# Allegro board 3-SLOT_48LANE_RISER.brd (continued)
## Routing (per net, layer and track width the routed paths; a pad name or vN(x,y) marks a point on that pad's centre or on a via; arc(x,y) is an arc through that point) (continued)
GND_L:
  vias: v2(-18.72,363.74) v2(-18.72,362.74) v2(-18.72,361.74) v2(-18.72,360.74) v2(-18.72,359.74) v2(-18.72,358.74) v2(-18.72,357.74) v2(-18.72,356.74) v2(-18.72,355.74) v2(-18.72,354.74) v2(-18.72,353.74) v2(-18.72,352.74) v2(-18.72,351.74) v2(-18.72,350.74) v2(-18.72,349.74) v2(-18.72,348.74) v2(-18.72,347.74) v2(-18.72,346.74) v2(-18.72,345.74) v2(-18.72,344.74) v2(-18.72,343.74) v2(-18.72,342.74) v2(-18.72,341.74) v2(-18.72,340.74) v2(-18.72,339.74) v2(-18.72,338.74) v2(-18.72,337.74) v2(-18.72,336.74) v2(-18.72,335.74) v2(-18.72,334.74) v2(-18.72,333.74) v2(-18.72,332.74) v2(-18.72,331.74) v2(-18.72,330.74) v2(-18.72,329.74) v2(-18.72,328.74) v2(-18.72,327.74) v2(-18.72,326.74) v2(-18.72,325.74) v2(-18.72,324.74) v2(-18.72,323.74) v2(-18.72,322.74) v2(-18.72,321.74) v2(-18.72,320.74) v2(-18.72,319.74) v2(-18.72,318.74) v2(-18.72,317.74) v2(-18.72,316.74) v2(-18.72,315.74) v2(-18.72,314.74) v2(-18.72,313.74) v2(-18.72,312.74) v2(-18.72,311.74) v2(-18.72,310.74) v2(-18.72,309.74) v2(-18.72,308.74) v2(-18.72,307.74) v2(-18.72,306.74) v2(-18.72,305.74) v2(-18.72,304.74) v2(-18.72,303.74) v2(-18.72,302.74) v2(-18.72,301.74) v2(-18.72,300.74) v2(-18.72,299.74) v2(-18.72,298.74) v2(-18.72,297.74) v2(-18.72,296.74) v2(-18.72,295.74) v2(-18.72,294.74) v2(-18.72,293.74) v2(-18.72,292.74) v2(-18.72,291.74) v2(-18.72,290.74) v2(-18.72,289.74) v2(-18.72,288.74) v2(-18.72,287.74) v2(-18.72,286.74) v2(-18.72,285.74) v2(-18.72,284.74) v2(-18.72,283.74) v2(-18.72,282.74) v2(-18.72,281.74) v2(-18.72,280.74) v2(-18.72,279.74) v2(-18.72,278.74) v2(-18.72,277.74) v2(-18.72,276.74) v2(-18.72,275.74) v2(-18.72,274.74) v2(-18.72,273.74) v2(-18.72,272.74) v2(-18.72,271.74) v2(-18.72,270.74) v2(-18.72,269.74) v2(-18.72,268.74) v2(-18.72,267.74) v2(-18.72,266.74) v2(-18.72,265.74) v2(-18.72,264.74) v2(-18.72,263.74) v2(-18.72,262.74) v2(-18.72,261.74) v2(-18.72,260.74) v2(-18.72,259.74) v2(-18.72,258.74) v2(-18.72,257.74) v2(-18.72,256.74) v2(-18.72,255.74) v2(-18.72,254.74) v2(-18.72,253.74) v2(-18.72,252.74) v2(-18.72,251.74) v2(-18.72,250.74) v2(-18.72,249.74) v2(-18.72,248.74) v2(-18.72,247.74) v2(-18.72,246.74) v2(-18.72,245.74) v2(-18.72,244.74) v2(-18.72,243.74) v2(-18.72,242.74) v2(-18.72,241.74) v2(-18.72,240.74) v2(-18.72,239.74) v2(-18.72,238.74) v2(-18.72,237.74) v2(-18.72,236.74) v2(-18.72,235.74) v2(-18.72,234.74) v2(-18.72,233.74) v2(-18.72,232.74) v2(-18.72,231.74) v2(-18.72,230.74) v2(-18.72,229.74) v2(-18.72,228.74) v2(-18.72,227.74) v2(-18.72,226.74) v2(-18.72,225.74) v2(-18.72,224.74) v2(-18.72,223.74) v2(-18.72,222.74) v2(-18.72,221.74) v2(-18.72,220.74) v2(-18.72,219.74) v2(-18.72,218.74) v2(-18.72,217.74) v2(-18.72,216.74) v2(-18.72,215.74) v2(-18.72,214.74) v2(-18.72,213.74) v2(-18.72,212.74) v2(-18.72,211.74) v2(-18.72,210.74) v2(-18.72,209.74) v2(-18.72,208.74) v2(-18.72,207.74) v2(-18.72,206.74) v2(-18.72,205.74) v2(-18.72,204.74) v2(-18.72,203.74) v2(-18.72,202.74) v2(-18.72,201.74) v2(-18.72,200.74) v2(-18.72,199.74) v2(-18.72,198.74) v2(-18.72,197.74) v2(-18.72,196.74) v2(-18.72,195.74) v2(-18.72,194.74) v2(-18.72,193.74) v2(-18.72,192.74) v2(-18.72,191.74) v2(-18.72,190.74) v2(-18.72,189.74) v2(-18.72,188.74) v2(-18.72,187.74) v2(-18.72,186.74) v2(-18.72,185.74) v2(-18.72,184.74) v2(-18.72,183.74) v2(-18.72,182.74) v2(-18.72,181.74) v2(-18.72,180.74) v2(-18.72,179.74) v2(-18.72,178.74) v2(-18.72,177.74) v2(-18.72,176.74) v2(-18.72,175.74) v2(-18.72,174.74) v2(-18.72,173.74) v2(-18.72,172.74) v2(-18.72,171.74) v2(-18.72,170.74) v2(-18.72,169.74) v2(-18.72,168.74) v2(-18.72,167.74) v2(-18.72,166.74) v2(-18.72,165.74) v2(-18.72,164.74) v2(-18.72,163.74) v2(-18.72,162.74) v2(-18.72,161.74) v2(-18.72,160.74) v2(-18.72,159.74) v2(-18.72,158.74) v2(-18.72,157.74) v2(-18.72,156.74) v2(-18.72,155.74) v2(-18.72,154.74) v2(-18.72,153.74) v2(-18.72,152.74) v2(-18.72,151.74) v2(-18.72,150.74) v2(-18.72,149.74) v2(-18.72,148.74) v2(-18.72,147.74) v2(-18.72,146.74) v2(-18.72,145.74) v2(-18.72,144.74) v2(-18.72,143.74) v2(-18.72,142.74) v2(-18.72,141.74) v2(-18.72,140.74) v2(-18.72,139.74) v2(-18.72,138.74) v2(-18.72,137.74) v2(-18.72,136.74) v2(-18.72,135.74) v2(-18.72,134.74) v2(-18.72,133.74) v2(-18.72,132.74) v2(-18.72,131.74) v2(-18.72,130.74) v2(-18.72,129.74) v2(-18.72,128.74) v2(-18.72,127.74) v2(-18.72,126.74) v2(-18.72,125.74) v2(-18.72,124.74) v2(-18.72,123.74) v2(-18.72,122.74) v2(-18.72,121.74) v2(-18.72,120.74) v2(-18.72,119.74) v2(-18.72,118.74) v2(-18.72,117.74) v2(-18.72,116.74) v2(-18.72,115.74) v2(-18.72,114.74) v2(-18.72,113.74) v2(-18.72,112.74) v2(-18.72,111.74) v2(-18.72,110.74) v2(-18.72,109.74) v2(-18.72,108.74) v2(-18.72,107.74) v2(-18.72,106.74) v2(-18.72,105.74) v2(-18.72,104.74) v2(-18.72,103.74) v2(-18.72,102.74) v2(-18.72,101.74) v2(-18.72,100.74) v2(-18.72,99.74) v2(-18.72,98.74) v2(-18.72,97.74) v2(-18.72,96.74) v2(-18.72,95.74) v2(-18.72,94.74) v2(-18.72,93.74) v2(-18.72,92.74) v2(-18.72,91.74) v2(-18.72,90.74) v2(-18.72,89.74) v2(-18.72,88.74) v2(-18.72,87.74) v2(-18.72,86.74) v2(-18.72,85.74) v2(-18.72,84.74) v2(-18.72,83.74) v2(-18.72,82.74) v2(-18.72,81.74) v2(-18.72,80.74) v2(-18.72,79.74) v2(-18.72,78.74) v2(-18.72,77.74) v2(-18.72,76.74) v2(-18.72,75.74) v2(-18.72,74.74) v2(-18.72,73.74) v2(-18.72,72.74) v2(-18.72,71.74) v2(-18.72,70.74) v2(-18.72,69.74) v2(-18.72,68.74) v2(-18.72,67.74) v2(-18.72,66.74) v2(-18.72,65.74) v2(-18.72,64.74) v2(-18.72,63.74) v2(-18.72,62.74) v2(-18.72,61.74) v2(-18.72,60.74) v2(-18.72,59.74) v2(-18.72,58.74) v2(-18.72,57.74) v2(-18.72,56.74) v2(-18.72,55.74) v2(-18.72,54.74) v2(-18.72,53.74) v2(-18.72,52.74) v2(-18.72,51.74) v2(-18.72,50.74) v2(-18.72,49.74) v2(-18.72,48.74) v2(-18.72,47.74) v2(-18.72,46.74) v2(-18.72,45.74) v2(-18.72,44.74) v2(-18.72,43.74) v2(-18.72,42.74) v2(-18.72,41.74) v2(-18.72,40.74) v2(-18.72,39.74) v2(-18.72,38.74) v2(-18.72,37.74) v2(-18.72,36.74) v2(-18.72,35.74) v2(-18.72,34.74) v2(-18.72,33.74) v2(-18.72,32.74) v2(-18.72,31.74) v2(-18.72,30.74) v2(-18.72,29.74) v2(-18.72,28.74) v2(-18.72,27.74) v2(-18.72,26.74) v2(-18.72,25.74) v2(-18.72,24.74) v2(-18.72,23.74) v2(-18.72,22.74) v2(-18.72,21.74) v2(-18.72,20.74) v2(-18.72,19.74) v2(-18.72,18.74) v2(-18.72,17.74) v2(-18.72,16.74) v2(-18.72,15.74) v2(-18.72,14.74) v2(-18.72,13.74) v2(-18.72,12.74) v2(-18.72,11.74) v2(-18.72,10.74) v2(-18.72,9.74) v2(-18.72,8.74) v2(-18.72,7.74) v2(-18.72,6.74) v2(-18.72,5.74) v2(-18.72,4.74) v2(-18.72,3.74) v2(-18.72,2.74) v2(-18.72,1.74) v2(-18.72,0.74) v2(-18.72,-0.26) v2(-18.72,-1.26) v2(-18.72,-2.26) v2(-18.72,-3.26) v2(-18.72,-4.26) v2(-18.72,-5.26) v2(-18.72,-6.26) v2(-18.72,-7.26) v2(-18.72,-8.26) v2(-17.1,65.8) v2(-17.1,64.8) v2(-17.1,63.8) v2(-17.1,62.8) v2(-17.1,61.8) v2(-17.1,60.8) v2(-17.1,59.8) v2(-17.1,58.8) v2(-17.1,57.8) v2(-17.1,56.8) v2(-17.1,55.8) v2(-17.1,54.8) v2(-17.1,53.8) v2(-17.1,52.8) v2(-17.1,51.8) v2(-17.1,50.8) v2(-16.97,299.48) v2(-16.97,298.48) v2(-16.97,297.48) v2(-16.97,296.48) v2(-16.97,295.48) v2(-16.97,294.48) v2(-16.97,293.48) v2(-16.97,292.48) v2(-16.97,291.48) v2(-16.97,290.48) v2(-16.97,289.48) v2(-16.97,288.48) v2(-16.97,287.48) v2(-16.97,286.48) v2(-16.97,285.48) v2(-16.97,284.48) v2(-16.97,237.38) v2(-16.97,236.38) v2(-16.97,235.38) v2(-16.97,234.38) v2(-16.97,233.38) v2(-16.97,232.38) v2(-16.97,231.38) v2(-16.97,230.38) v2(-16.97,229.38) v2(-16.97,228.38) v2(-16.97,227.38) v2(-16.97,4.21) v2(-16.97,3.21) v2(-16.97,2.21) v2(-16.97,1.21) v2(-16.97,0.21) v2(-16.97,-0.79) v2(-16.97,-1.79) v2(-16.97,-2.79) v2(-16.97,-3.79) v2(-16.97,-4.79) v2(-16.97,-5.79) v2(-16.97,-6.79) v2(-16.97,-7.79) v2(-16.85,180.36) v2(-16.85,179.36) v2(-16.85,178.36) v2(-16.85,177.36) v2(-16.85,176.36) v2(-16.85,175.36) v2(-16.85,174.36) v2(-16.85,173.36) v2(-16.85,172.36) v2(-16.85,171.36) v2(-16.85,170.36) v2(-16.85,122.95) v2(-16.85,121.95) v2(-16.85,120.95) v2(-16.85,119.95) v2(-16.85,118.95) v2(-16.85,117.95) v2(-16.85,116.95) v2(-16.85,115.95) v2(-16.85,114.95) v2(-16.85,113.95) v2(-16.85,112.95) v2(-16.72,363.74) v2(-16.72,362.74) v2(-16.72,361.74) v2(-16.72,360.74) v2(-16.72,359.74) v2(-16.72,358.74) v2(-16.72,357.74) v2(-16.72,356.74) v2(-16.72,355.74) v2(-16.72,354.74) v2(-16.72,353.74) v2(-16.72,352.74) v2(-16.72,351.74) v2(-16.72,350.74) v2(-16.72,349.74) v2(-16.72,348.74) v2(-16.72,347.74) v2(-16.72,346.74) v2(-15.1,65.8) v2(-15.1,64.8) v2(-15.1,63.8) v2(-15.1,62.8) v2(-15.1,61.8) v2(-15.1,60.8) v2(-15.1,59.8) v2(-15.1,58.8) v2(-15.1,57.8) v2(-15.1,56.8) v2(-15.1,55.8) v2(-15.1,54.8) v2(-15.1,53.8) v2(-15.1,52.8) v2(-15.1,51.8) v2(-15.1,50.8) v2(-14.97,299.48) v2(-14.97,298.48) v2(-14.97,297.48) v2(-14.97,296.48) v2(-14.97,295.48) v2(-14.97,294.48) v2(-14.97,293.48) v2(-14.97,292.48) v2(-14.97,291.48) v2(-14.97,290.48) v2(-14.97,289.48) v2(-14.97,288.48) v2(-14.97,287.48) v2(-14.97,286.48) v2(-14.97,285.48) v2(-14.97,284.48) v2(-14.97,237.38) v2(-14.97,236.38) v2(-14.97,235.38) v2(-14.97,234.38) v2(-14.97,233.38) v2(-14.97,232.38) v2(-14.97,231.38) v2(-14.97,230.38) v2(-14.97,229.38) v2(-14.97,228.38) v2(-14.97,227.38) v2(-14.97,4.21) v2(-14.97,3.21) v2(-14.97,2.21) v2(-14.97,1.21) v2(-14.97,0.21) v2(-14.97,-0.79) v2(-14.97,-1.79) v2(-14.97,-2.79) v2(-14.97,-3.79) v2(-14.97,-4.79) v2(-14.97,-5.79) v2(-14.97,-6.79) v2(-14.97,-7.79) v2(-14.85,180.36) v2(-14.85,179.36) v2(-14.85,178.36) v2(-14.85,177.36) v2(-14.85,176.36) v2(-14.85,175.36) v2(-14.85,174.36) v2(-14.85,173.36) v2(-14.85,172.36) v2(-14.85,171.36) v2(-14.85,170.36) v2(-14.85,122.95) v2(-14.85,121.95) v2(-14.85,120.95) v2(-14.85,119.95) v2(-14.85,118.95) v2(-14.85,117.95) v2(-14.85,116.95) v2(-14.85,115.95) v2(-14.85,114.95) v2(-14.85,113.95) v2(-14.85,112.95) v2(-14.72,363.74) v2(-14.72,362.74) v2(-14.72,361.74) v2(-14.72,360.74) v2(-14.72,359.74) v2(-14.72,358.74) v2(-14.72,357.74) v2(-14.72,356.74) v2(-14.72,355.74) v2(-14.72,354.74) v2(-14.72,353.74) v2(-14.72,352.74) v2(-14.72,351.74) v2(-14.72,350.74) v2(-14.72,349.74) v2(-14.72,348.74) v2(-14.72,347.74) v2(-14.72,346.74) v2(-13.1,65.8) v2(-13.1,64.8) v2(-13.1,63.8) v2(-13.1,62.8) v2(-13.1,61.8) v2(-13.1,60.8) v2(-13.1,59.8) v2(-13.1,58.8) v2(-13.1,57.8) v2(-13.1,56.8) v2(-13.1,55.8) v2(-13.1,54.8) v2(-13.1,53.8) v2(-13.1,52.8) v2(-13.1,51.8) v2(-13.1,50.8) v2(-12.97,299.48) v2(-12.97,298.48) v2(-12.97,297.48) v2(-12.97,296.48) v2(-12.97,295.48) v2(-12.97,294.48) v2(-12.97,293.48) v2(-12.97,292.48) v2(-12.97,291.48) v2(-12.97,290.48) v2(-12.97,289.48) v2(-12.97,288.48) v2(-12.97,287.48) v2(-12.97,286.48) v2(-12.97,285.48) v2(-12.97,284.48) v2(-12.97,237.38) v2(-12.97,236.38) v2(-12.97,235.38) v2(-12.97,234.38) v2(-12.97,233.38) v2(-12.97,232.38) v2(-12.97,231.38) v2(-12.97,230.38) v2(-12.97,229.38) v2(-12.97,228.38) v2(-12.97,227.38) v2(-12.97,4.21) v2(-12.97,3.21) v2(-12.97,2.21) v2(-12.97,1.21) v2(-12.97,0.21) v2(-12.97,-0.79) v2(-12.97,-1.79) v2(-12.97,-2.79) v2(-12.97,-3.79) v2(-12.97,-4.79) v2(-12.97,-5.79) v2(-12.97,-6.79) v2(-12.97,-7.79) v2(-12.85,180.36) v2(-12.85,179.36) v2(-12.85,178.36) v2(-12.85,177.36) v2(-12.85,176.36) v2(-12.85,175.36) v2(-12.85,174.36) v2(-12.85,173.36) v2(-12.85,172.36) v2(-12.85,171.36) v2(-12.85,170.36) v2(-12.85,122.95) v2(-12.85,121.95) v2(-12.85,120.95) v2(-12.85,119.95) v2(-12.85,118.95) v2(-12.85,117.95) v2(-12.85,116.95) v2(-12.85,115.95) v2(-12.85,114.95) v2(-12.85,113.95) v2(-12.85,112.95) v2(-12.72,363.74) v2(-12.72,362.74) v2(-12.72,361.74) v2(-12.72,360.74) v2(-12.72,359.74) v2(-12.72,358.74) v2(-12.72,357.74) v2(-12.72,356.74) v2(-12.72,355.74) v2(-12.72,354.74) v2(-12.72,353.74) v2(-12.72,352.74) v2(-12.72,351.74) v2(-12.72,350.74) v2(-12.72,349.74) v2(-12.72,348.74) v2(-12.72,347.74) v2(-12.72,346.74) v2(-11.1,65.8) v2(-11.1,64.8) v2(-11.1,63.8) v2(-11.1,62.8) v2(-11.1,61.8) v2(-11.1,60.8) v2(-11.1,59.8) v2(-11.1,58.8) v2(-11.1,57.8) v2(-11.1,56.8) v2(-11.1,55.8) v2(-11.1,54.8) v2(-11.1,53.8) v2(-11.1,52.8) v2(-11.1,51.8) v2(-11.1,50.8) v2(-10.97,299.48) v2(-10.97,298.48) v2(-10.97,297.48) v2(-10.97,296.48) v2(-10.97,295.48) v2(-10.97,294.48) v2(-10.97,293.48) v2(-10.97,292.48) v2(-10.97,291.48) v2(-10.97,290.48) v2(-10.97,289.48) v2(-10.97,288.48) v2(-10.97,287.48) v2(-10.97,286.48) v2(-10.97,285.48) v2(-10.97,284.48) v2(-10.97,237.38) v2(-10.97,236.38) v2(-10.97,235.38) v2(-10.97,234.38) v2(-10.97,233.38) v2(-10.97,232.38) v2(-10.97,231.38) v2(-10.97,230.38) v2(-10.97,229.38) v2(-10.97,228.38) v2(-10.97,227.38) v2(-10.97,4.21) v2(-10.97,3.21) v2(-10.97,2.21) v2(-10.97,1.21) v2(-10.97,0.21) v2(-10.97,-0.79) v2(-10.97,-1.79) v2(-10.97,-2.79) v2(-10.97,-3.79) v2(-10.97,-4.79) v2(-10.97,-5.79) v2(-10.97,-6.79) v2(-10.97,-7.79) v2(-10.85,180.36) v2(-10.85,179.36) v2(-10.85,178.36) v2(-10.85,177.36) v2(-10.85,176.36) v2(-10.85,175.36) v2(-10.85,174.36) v2(-10.85,173.36) v2(-10.85,172.36) v2(-10.85,171.36) v2(-10.85,170.36) v2(-10.85,122.95) v2(-10.85,121.95) v2(-10.85,120.95) v2(-10.85,119.95) v2(-10.85,118.95) v2(-10.85,117.95) v2(-10.85,116.95) v2(-10.85,115.95) v2(-10.85,114.95) v2(-10.85,113.95) v2(-10.85,112.95) v2(-10.72,363.74) v2(-10.72,362.74) v2(-10.72,361.74) v2(-10.72,360.74) v2(-10.72,359.74) v2(-10.72,358.74) v2(-10.72,357.74) v2(-10.72,356.74) v2(-10.72,355.74) v2(-10.72,354.74) v2(-10.72,353.74) v2(-10.72,352.74) v2(-10.72,351.74) v2(-10.72,350.74) v2(-10.72,349.74) v2(-10.72,348.74) v2(-10.72,347.74) v2(-10.72,346.74) v2(-9.1,65.8) v2(-9.1,64.8) v2(-9.1,63.8) v2(-9.1,62.8) v2(-9.1,61.8) v2(-9.1,60.8) v2(-9.1,59.8) v2(-9.1,58.8) v2(-9.1,57.8) v2(-9.1,56.8) v2(-9.1,55.8) v2(-9.1,54.8) v2(-9.1,53.8) v2(-9.1,52.8) v2(-9.1,51.8) v2(-9.1,50.8) v2(-8.97,299.48) v2(-8.97,298.48) v2(-8.97,297.48) v2(-8.97,296.48) v2(-8.97,295.48) v2(-8.97,294.48) v2(-8.97,293.48) v2(-8.97,292.48) v2(-8.97,291.48) v2(-8.97,290.48) v2(-8.97,289.48) v2(-8.97,288.48) v2(-8.97,287.48) v2(-8.97,286.48) v2(-8.97,285.48) v2(-8.97,284.48) v2(-8.97,237.38) v2(-8.97,236.38) v2(-8.97,235.38) v2(-8.97,234.38) v2(-8.97,233.38) v2(-8.97,232.38) v2(-8.97,231.38) v2(-8.97,230.38) v2(-8.97,229.38) v2(-8.97,228.38) v2(-8.97,227.38) v2(-8.97,4.21) v2(-8.97,3.21) v2(-8.97,2.21) v2(-8.97,1.21) v2(-8.97,0.21) v2(-8.97,-0.79) v2(-8.97,-1.79) v2(-8.97,-2.79) v2(-8.97,-3.79) v2(-8.97,-4.79) v2(-8.97,-5.79) v2(-8.97,-6.79) v2(-8.97,-7.79) v2(-8.85,180.36) v2(-8.85,179.36) v2(-8.85,178.36) v2(-8.85,177.36) v2(-8.85,176.36) v2(-8.85,175.36) v2(-8.85,174.36) v2(-8.85,173.36) v2(-8.85,172.36) v2(-8.85,171.36) v2(-8.85,170.36) v2(-8.85,122.95) v2(-8.85,121.95) v2(-8.85,120.95) v2(-8.85,119.95) v2(-8.85,118.95) v2(-8.85,117.95) v2(-8.85,116.95) v2(-8.85,115.95) v2(-8.85,114.95) v2(-8.85,113.95) v2(-8.85,112.95) v2(-8.72,363.74) v2(-8.72,362.74) v2(-8.72,361.74) v2(-8.72,360.74) v2(-8.72,359.74) v2(-8.72,358.74) v2(-8.72,357.74) v2(-8.72,356.74) v2(-8.72,355.74) v2(-8.72,354.74) v2(-8.72,353.74) v2(-8.72,352.74) v2(-8.72,351.74) v2(-8.72,350.74) v2(-8.72,349.74) v2(-8.72,348.74) v2(-8.72,347.74) v2(-8.72,346.74) v2(-8.18,164.21) v2(-7.42,164.21) v2(-7.1,65.8) v2(-7.1,64.8) v2(-7.1,63.8) v2(-7.1,62.8) v2(-7.1,61.8) v2(-7.1,60.8) v2(-7.1,59.8) v2(-7.1,58.8) v2(-7.1,57.8) v2(-7.1,56.8) v2(-7.1,55.8) v2(-7.1,54.8) v2(-7.1,53.8) v2(-7.1,52.8) v2(-7.1,51.8) v2(-7.1,50.8) v2(-6.97,299.48) v2(-6.97,298.48) v2(-6.97,297.48) v2(-6.97,296.48) v2(-6.97,295.48) v2(-6.97,294.48) v2(-6.97,293.48) v2(-6.97,292.48) v2(-6.97,291.48) v2(-6.97,290.48) v2(-6.97,289.48) v2(-6.97,288.48) v2(-6.97,287.48) v2(-6.97,286.48) v2(-6.97,285.48) v2(-6.97,284.48) v2(-6.97,237.38) v2(-6.97,236.38) v2(-6.97,235.38) v2(-6.97,234.38) v2(-6.97,233.38) v2(-6.97,232.38) v2(-6.97,231.38) v2(-6.97,230.38) v2(-6.97,229.38) v2(-6.97,228.38) v2(-6.97,227.38) v2(-6.97,4.21) v2(-6.97,3.21) v2(-6.97,2.21) v2(-6.97,1.21) v2(-6.97,0.21) v2(-6.97,-0.79) v2(-6.97,-1.79) v2(-6.97,-2.79) v2(-6.97,-3.79) v2(-6.97,-4.79) v2(-6.97,-5.79) v2(-6.97,-6.79) v2(-6.97,-7.79) v2(-6.85,180.36) v2(-6.85,179.36) v2(-6.85,178.36) v2(-6.85,177.36) v2(-6.85,176.36) v2(-6.85,175.36) v2(-6.85,174.36) v2(-6.85,173.36) v2(-6.85,172.36) v2(-6.85,171.36) v2(-6.85,170.36) v2(-6.85,122.95) v2(-6.85,121.95) v2(-6.85,120.95) v2(-6.85,119.95) v2(-6.85,118.95) v2(-6.85,117.95) v2(-6.85,116.95) v2(-6.85,115.95) v2(-6.85,114.95) v2(-6.85,113.95) v2(-6.85,112.95) v2(-6.72,363.74) v2(-6.72,362.74) v2(-6.72,361.74) v2(-6.72,358.74) v2(-6.72,357.74) v2(-6.72,356.74) v2(-6.72,355.74) v2(-6.72,354.74) v2(-6.72,353.74) v2(-6.72,352.74) v2(-6.72,351.74) v2(-6.72,348.74) v2(-6.72,347.74) v2(-6.72,346.74) v2(-4.96,65.8) v2(-4.96,64.8) v2(-4.96,63.8) v2(-4.96,62.8) v2(-4.96,61.8) v2(-4.96,60.8) v2(-4.96,59.8) v2(-4.96,58.8) v2(-4.96,57.8) v2(-4.96,56.8) v2(-4.96,55.8) v2(-4.96,54.8) v2(-4.96,53.8) v2(-4.96,52.8) v2(-4.96,51.8) v2(-4.96,50.8) v2(-4.83,299.48) v2(-4.83,298.48) v2(-4.83,297.48) v2(-4.83,296.48) v2(-4.83,295.48) v2(-4.83,294.48) v2(-4.83,293.48) v2(-4.83,292.48) v2(-4.83,291.48) v2(-4.83,290.48) v2(-4.83,289.48) v2(-4.83,288.48) v2(-4.83,287.48) v2(-4.83,286.48) v2(-4.83,285.48) v2(-4.83,284.48) v2(-4.83,237.38) v2(-4.83,236.38) v2(-4.83,235.38) v2(-4.83,234.38) v2(-4.83,233.38) v2(-4.83,232.38) v2(-4.83,231.38) v2(-4.83,230.38) v2(-4.83,229.38) v2(-4.83,228.38) v2(-4.83,227.38) v2(-4.83,4.21) v2(-4.83,3.21) v2(-4.83,-1.79) v2(-4.83,-6.79) v2(-4.83,-7.79) v2(-4.7,180.36) v2(-4.7,179.36) v2(-4.7,178.36) v2(-4.7,177.36) v2(-4.7,176.36) v2(-4.7,175.36) v2(-4.7,174.36) v2(-4.7,173.36) v2(-4.7,172.36) v2(-4.7,171.36) v2(-4.7,170.36) v2(-4.7,122.95) v2(-4.7,121.95) v2(-4.7,120.95) v2(-4.7,119.95) v2(-4.7,118.95) v2(-4.7,117.95) v2(-4.7,116.95) v2(-4.7,115.95) v2(-4.7,114.95) v2(-4.7,113.95) v2(-4.7,112.95) v2(-4.58,363.74) v2(-4.58,362.74) v2(-4.58,357.74) v2(-4.58,356.74) v2(-4.58,355.74) v2(-4.58,354.74) v2(-4.58,353.74) v2(-4.58,352.74) v2(-4.58,347.74) v2(-4.58,346.74) v2(-2.97,363.74) v2(-2.97,362.74) v2(-2.97,361.74) v2(-2.97,360.74) v2(-2.97,359.74) v2(-2.97,358.74) v2(-2.97,357.74) v2(-2.97,356.74) v2(-2.97,355.74) v2(-2.97,354.74) v2(-2.97,353.74) v2(-2.97,352.74) v2(-2.97,351.74) v2(-2.97,350.74) v2(-2.97,349.74) v2(-2.97,348.74) v2(-2.97,347.74) v2(-2.97,346.74) v2(-2.97,345.74) v2(-2.97,344.74) v2(-2.97,343.74) v2(-2.97,342.74) v2(-2.97,341.74) v2(-2.97,340.74) v2(-2.97,339.74) v2(-2.97,338.74) v2(-2.97,337.74) v2(-2.97,336.74) v2(-2.97,335.74) v2(-2.97,334.74) v2(-2.97,333.74) v2(-2.97,332.74) v2(-2.97,331.74) v2(-2.97,330.74) v2(-2.97,329.74) v2(-2.97,328.74) v2(-2.97,327.74) v2(-2.97,326.74) v2(-2.97,325.74) v2(-2.97,324.74) v2(-2.97,323.74) v2(-2.97,322.74) v2(-2.97,321.74) v2(-2.97,320.74) v2(-2.97,319.74) v2(-2.97,318.74) v2(-2.97,317.74) v2(-2.97,316.74) v2(-2.97,315.74) v2(-2.97,314.74) v2(-2.97,313.74) v2(-2.97,312.74) v2(-2.97,311.74) v2(-2.97,310.74) v2(-2.97,309.74) v2(-2.97,308.74) v2(-2.97,307.74) v2(-2.97,306.74) v2(-2.97,305.74) v2(-2.97,304.74) v2(-2.97,303.74) v2(-2.97,302.74) v2(-2.97,301.74) v2(-2.97,300.74) v2(-2.97,299.74) v2(-2.97,298.74) v2(-2.97,297.74) v2(-2.97,296.74) v2(-2.97,295.74) v2(-2.97,294.74) v2(-2.97,293.74) v2(-2.97,292.74) v2(-2.97,291.74) v2(-2.97,290.74) v2(-2.97,289.74) v2(-2.97,288.74) v2(-2.97,287.74) v2(-2.97,286.74) v2(-2.97,285.74) v2(-2.97,284.74) v2(-2.97,283.74) v2(-2.97,282.74) v2(-2.97,281.74) v2(-2.97,280.74) v2(-2.97,279.74) v2(-2.97,278.74) v2(-2.97,277.74) v2(-2.97,276.74) v2(-2.97,275.74) v2(-2.97,274.74) v2(-2.97,273.74) v2(-2.97,272.74) v2(-2.97,271.74) v2(-2.97,270.74) v2(-2.97,269.74) v2(-2.97,268.74) v2(-2.97,267.74) v2(-2.97,266.74) v2(-2.97,265.74) v2(-2.97,264.74) v2(-2.97,263.74) v2(-2.97,262.74) v2(-2.97,261.74) v2(-2.97,260.74) v2(-2.97,259.74) v2(-2.97,258.74) v2(-2.97,257.74) v2(-2.97,256.74) v2(-2.97,255.74) v2(-2.97,254.74) v2(-2.97,253.74) v2(-2.97,252.74) v2(-2.97,251.74) v2(-2.97,250.74) v2(-2.97,249.74) v2(-2.97,248.74) v2(-2.97,247.74) v2(-2.97,246.74) v2(-2.97,245.74) v2(-2.97,244.74) v2(-2.97,243.74) v2(-2.97,242.74) v2(-2.97,241.74) v2(-2.97,240.74) v2(-2.97,239.74) v2(-2.97,238.74) v2(-2.97,237.74) v2(-2.97,236.74) v2(-2.97,235.74) v2(-2.97,234.74) v2(-2.97,233.74) v2(-2.97,232.74) v2(-2.97,231.74) v2(-2.97,230.74) v2(-2.97,229.74) v2(-2.97,228.74) v2(-2.97,227.74) v2(-2.97,226.74) v2(-2.97,225.74) v2(-2.97,224.74) v2(-2.97,223.74) v2(-2.97,222.74) v2(-2.97,221.74) v2(-2.97,220.74) v2(-2.97,219.74) v2(-2.97,218.74) v2(-2.97,217.74) v2(-2.97,216.74) v2(-2.97,215.74) v2(-2.97,214.74) v2(-2.97,213.74) v2(-2.97,212.74) v2(-2.97,211.74) v2(-2.97,210.74) v2(-2.97,209.74) v2(-2.97,208.74) v2(-2.97,207.74) v2(-2.97,206.74) v2(-2.97,205.74) v2(-2.97,204.74) v2(-2.97,203.74) v2(-2.97,202.74) v2(-2.97,201.74) v2(-2.97,200.74) v2(-2.97,199.74) v2(-2.97,198.74) v2(-2.97,197.74) v2(-2.97,196.74) v2(-2.97,195.74) v2(-2.97,194.74) v2(-2.97,193.74) v2(-2.97,192.74) v2(-2.97,191.74) v2(-2.97,190.74) v2(-2.97,189.74) v2(-2.97,188.74) v2(-2.97,187.74) v2(-2.97,186.74) v2(-2.97,185.74) v2(-2.97,184.74) v2(-2.97,183.74) v2(-2.97,182.74) v2(-2.97,181.74) v2(-2.97,180.74) v2(-2.97,179.74) v2(-2.97,178.74) v2(-2.97,177.74) v2(-2.97,176.74) v2(-2.97,175.74) v2(-2.97,174.74) v2(-2.97,173.74) v2(-2.97,172.74) v2(-2.97,171.74) v2(-2.97,170.74) v2(-2.97,169.74) v2(-2.97,168.74) v2(-2.97,167.74) v2(-2.97,166.74) v2(-2.97,165.74) v2(-2.97,164.74) v2(-2.97,163.74) v2(-2.97,162.74) v2(-2.97,161.74) v2(-2.97,160.74) v2(-2.97,159.74) v2(-2.97,158.74) v2(-2.97,157.74) v2(-2.97,156.74) v2(-2.97,155.74) v2(-2.97,154.74) v2(-2.97,153.74) v2(-2.97,152.74) v2(-2.97,151.74) v2(-2.97,150.74) v2(-2.97,149.74) v2(-2.97,148.74) v2(-2.97,147.74) v2(-2.97,146.74) v2(-2.97,145.74) v2(-2.97,144.74) v2(-2.97,143.74) v2(-2.97,142.74) v2(-2.97,141.74) v2(-2.97,140.74) v2(-2.97,139.74) v2(-2.97,138.74) v2(-2.97,137.74) v2(-2.97,136.74) v2(-2.97,135.74) v2(-2.97,134.74) v2(-2.97,133.74) v2(-2.97,132.74) v2(-2.97,131.74) v2(-2.97,130.74) v2(-2.97,129.74) v2(-2.97,128.74) v2(-2.97,127.74) v2(-2.97,126.74) v2(-2.97,125.74) v2(-2.97,124.74) v2(-2.97,123.74) v2(-2.97,122.74) v2(-2.97,121.74) v2(-2.97,120.74) v2(-2.97,119.74) v2(-2.97,118.74) v2(-2.97,117.74) v2(-2.97,116.74) v2(-2.97,115.74) v2(-2.97,114.74) v2(-2.97,113.74) v2(-2.97,112.74) v2(-2.97,111.74) v2(-2.97,110.74) v2(-2.97,109.74) v2(-2.97,108.74) v2(-2.97,107.74) v2(-2.97,106.74) v2(-2.97,105.74) v2(-2.97,104.74) v2(-2.97,103.74) v2(-2.97,102.74) v2(-2.97,101.74) v2(-2.97,100.74) v2(-2.97,99.74) v2(-2.97,98.74) v2(-2.97,97.74) v2(-2.97,96.74) v2(-2.97,95.74) v2(-2.97,94.74) v2(-2.97,93.74) v2(-2.97,92.74) v2(-2.97,91.74) v2(-2.97,90.74) v2(-2.97,89.74) v2(-2.97,88.74) v2(-2.97,87.74) v2(-2.97,86.74) v2(-2.97,85.74) v2(-2.97,84.74) v2(-2.97,83.74) v2(-2.97,82.74) v2(-2.97,81.74) v2(-2.97,80.74) v2(-2.97,79.74) v2(-2.97,78.74) v2(-2.97,77.74) v2(-2.97,76.74) v2(-2.97,75.74) v2(-2.97,74.74) v2(-2.97,73.74) v2(-2.97,72.74) v2(-2.97,71.74) v2(-2.97,70.74) v2(-2.97,69.74) v2(-2.97,68.74) v2(-2.97,67.74) v2(-2.97,66.74) v2(-2.97,65.74) v2(-2.97,64.74) v2(-2.97,63.74) v2(-2.97,62.74) v2(-2.97,61.74) v2(-2.97,60.74) v2(-2.97,59.74) v2(-2.97,58.74) v2(-2.97,57.74) v2(-2.97,56.74) v2(-2.97,55.74) v2(-2.97,54.74) v2(-2.97,53.74) v2(-2.97,52.74) v2(-2.97,51.74) v2(-2.97,50.74) v2(-2.97,49.74) v2(-2.97,48.74) v2(-2.97,47.74) v2(-2.97,46.74) v2(-2.97,45.74) v2(-2.97,44.74) v2(-2.97,43.74) v2(-2.97,42.74) v2(-2.97,41.74) v2(-2.97,40.74) v2(-2.97,39.74) v2(-2.97,38.74) v2(-2.97,37.74) v2(-2.97,36.74) v2(-2.97,35.74) v2(-2.97,34.74) v2(-2.97,33.74) v2(-2.97,32.74) v2(-2.97,31.74) v2(-2.97,30.74) v2(-2.97,29.74) v2(-2.97,28.74) v2(-2.97,27.74) v2(-2.97,26.74) v2(-2.97,25.74) v2(-2.97,24.74) v2(-2.97,23.74) v2(-2.97,22.74) v2(-2.97,21.74) v2(-2.97,20.74) v2(-2.97,19.74) v2(-2.97,18.74) v2(-2.97,17.74) v2(-2.97,16.74) v2(-2.97,15.74) v2(-2.97,14.74) v2(-2.97,13.74) v2(-2.97,12.74) v2(-2.97,11.74) v2(-2.97,10.74) v2(-2.97,9.74) v2(-2.97,8.74) v2(-2.97,7.74) v2(-2.97,6.74) v2(-2.97,5.74) v2(-2.97,4.74) v2(-2.97,3.74) v2(-2.97,2.74) v2(-2.97,1.74) v2(-2.97,0.74) v2(-2.97,-0.26) v2(-2.97,-1.26) v2(-2.97,-2.26) v2(-2.97,-3.26) v2(-2.97,-4.26) v2(-2.97,-5.26) v2(-2.97,-6.26) v2(-2.97,-7.26) v2(-2.97,-8.26)
P0V9: length 287.7
  TOP w0.203: C18.1 v3(64.85,73.56) ; C271.1 v3(60.85,73.56) ; C402.1 v3(61.65,76.77) C430.1 ; C290.1 v3(61.65,72.76) ; C418.1 v3(64.05,74.36) ; C422.1 v3(60.05,76.77) ; C16.1 v3(63.25,79.17) C438.1 ; C22.1 v3(60.85,79.17) ; C20.1 v3(64.05,78.37) ; C279.1 v3(60.05,74.36) ; C273.1 v3(60.85,71.96) ; C9.1 v3(59.25,79.17) ; C269.1 v3(60.85,77.57) ; C287.1 v3(63.25,71.96) ; C275.1 v3(63.25,77.57) C283.1 ; C297.1 v3(63.25,73.56) ; C394.1 v3(63.25,75.16) ; C398.1 v3(60.05,78.37) ; C426.1 v3(60.85,75.16) ; C277.1 v3(64.05,72.76) ; C442.1 v3(59.25,73.56) ; C281.1 v3(60.05,72.76) ; C294.1 v3(61.65,74.36) ; C434.1 v3(64.05,76.77) ; C410.1 v3(61.65,78.37) ; C414.1 v3(64.85,75.16)
  TOP w0.254: v2(49.48,61.09) 49.45,61.09 48.56,60.2 47.32,60.2 PR433.2 ; 59.57,72.18 v3(59.25,71.96)
  TOP w0.381: R148.1 v2(258.19,29.92) ; C145.1 v5(71.45,65.02) ; C147.1 v5(73.23,64.41)
  TOP w0.762: v2(116.89,42.49) 80.9,42.49 73,50.39 61.95,50.39 61.16,51.18
  IN1 w0.254: v2(47.96,61.34) 48.21,61.59 48.21,63.66 49.58,65.02 53.42,65.02 53.43,65.01 53.84,65.01 54.21,64.64 59.05,64.64 62.26,67.85 62.26,72.16 v3(61.65,72.76)
  IN1 w0.762: v2(258.19,29.92) 257.68,29.41 187.68,29.41 171.6,45.49 119.89,45.49 v2(116.89,42.49)
  IN2 w0.254: v2(59.51,53.09) 62.18,53.09 66.35,48.92 69.7,48.92 69.95,48.67 v2(69.95,48.39)
  BOTTOM w0.254: v3(60.85,71.96) U1.P8 ; U1.L13 v3(64.05,76.77) U1.K14 ; v3(63.25,73.56) 62.85,73.96 U1.M10 ; U1.P14 61.25,77.17 v3(60.85,77.57) ; U1.K12 v3(64.85,75.16) ; U1.R9 v3(60.05,72.76) U1.T8 v3(59.25,71.96) ; PR430.2 69.95,47.63 v2(69.95,48.39) ; U1.M14 v3(63.25,77.57) 63.65,77.96 U1.L15 v3(64.05,78.37) U1.K16 ; U1.R11 v3(60.05,74.36) ; U1.P12 v3(60.85,75.16) ; U1.N11 v3(61.65,74.36) ; U1.N9 v3(61.65,72.76) ; PR433.2 47.57,59.94 47.96,59.94 48.21,60.2 48.21,61.09 v2(47.96,61.34) ; U1.L11 v3(64.05,74.36) ; U1.M12 v3(63.25,75.16) ; v3(60.85,79.17) 61.25,78.77 U1.P16 ; U1.T10 59.65,73.96 v3(59.25,73.56) ; U1.M16 v3(63.25,79.17) ; U1.R15 v3(60.05,78.37) ; U1.K10 v3(64.85,73.56) ; v3(60.85,73.56) 61.25,73.96 U1.P10 ; U1.T14 v3(60.05,76.77) U1.R13 U1.T12 ; U1.M8 62.85,72.36 v3(63.25,71.96) ; v3(59.25,79.17) 59.65,78.77 U1.T16 ; U1.L9 v3(64.05,72.76) U1.K8 ; U1.N13 v3(61.65,76.77) ; U1.N15 v3(61.65,78.37)
  vias: v2(23.19,89.66) v2(23.32,87.88) v2(23.32,86.36) v2(23.95,89.66) v2(24.08,87.88) v2(24.08,86.36) v2(24.72,89.66) v2(24.84,87.88) v2(24.84,86.36) v2(45.42,51.59) v2(45.92,52.07) v2(45.92,50.93) v2(46.18,52.96) v2(47.07,53.09) v2(48.46,53.09) v2(49.48,62.1) v2(49.61,53.09) v2(49.61,51.82) v2(49.61,50.67) v2(50.5,50.67) v2(50.62,53.09) v2(50.62,51.82) v2(50.75,63.12) v2(51.51,53.09) v2(51.69,62.03) v2(51.69,61.01) v2(52.66,53.09) v2(53.54,53.09) v2(53.85,61.93) v2(53.85,61.09) v2(54.43,53.09) v2(54.56,52.07) v2(54.56,50.67) v2(55.45,53.09) v2(55.45,52.07) v2(55.45,50.67) v2(56.72,53.09) v2(57.74,53.09) v2(59.79,51.97) v2(59.79,50.57) v4(48.08,51.18) v4(55.81,63.37) v4(58.22,51.74)
P0V9_A: length 48.5
  TOP w0.203: C164.1 v3(60.85,71.16) ; C150.1 v3(58.45,71.96) ; C19.1 v3(66.45,71.96) ; C141.1 v3(66.45,75.16) ; C15.1 v3(58.45,72.76) ; C144.1 v3(64.85,79.17) ; C146.1 v3(65.65,78.37) ; v3(65.65,72.76) C10.1 ; C161.1 v3(66.45,79.17) ; C142.1 v3(64.85,70.36) ; C21.1 v3(66.45,72.76) ; C4.1 v3(57.65,75.97) ; v3(58.45,79.17) C17.1 ; C151.1 v3(66.45,79.97) ; v3(58.45,74.36) C6.1 ; C163.1 v3(63.25,71.16) ; C2.1 v3(57.65,78.37) ; C148.1 v3(66.45,70.36) ; C14.1 v3(65.65,74.36) ; C162.1 v3(58.45,80.77) ; C5.1 v3(59.25,80.77) ; C7.1 v3(58.45,78.37)
  TOP w0.254: v3(63.25,79.97) 63.21,80.01 C406.1 ; v3(58.45,77.57) 59.57,77.76 59.57,77.77 C390.1 ; C143.1 v3(65.65,76.77) ; C194.1 v3(60.05,71.16)
  TOP w0.381: C11.1 v2(43.13,89.92) ; C8.1 v2(72.59,88.14) ; C188.1 v2(43.13,92.02) ; C3.1 v2(66.37,88.14) ; C177.1 v2(43.13,86.87) ; C12.1 v2(75.01,88.14) ; C184.1 v2(43.13,87.88) ; C149.1 v2(43.13,91.01) ; C13.1 v2(43.13,88.9) ; C160.1 v2(71.2,88.14)
  BOTTOM w0.254: v3(65.65,78.37) U1.H16 v3(66.45,79.17) ; v3(65.65,78.37) U1.H15 ; v3(65.65,78.37) U1.J15 ; v3(65.65,72.76) U1.H9 v3(66.45,72.76) U1.H8 v3(66.45,71.96) 66.06,71.57 U1.H7 v3(66.45,71.16) 66.06,70.76 U1.H6 v3(66.45,70.36) ; v3(65.65,72.76) 65.26,72.37 U1.J8 65.25,72.36 v3(64.85,71.96) U1.J7 ; v3(65.65,72.76) U1.J9 ; U1.N7 U1.M7 ; v3(58.45,72.76) 58.85,72.37 U1.U8 v3(58.45,71.96) ; U1.K17 64.46,79.56 v3(64.85,79.17) 65.25,78.77 U1.J16 ; U1.K6 v3(64.85,70.36) ; v3(58.45,80.77) U1.U18 v3(59.25,80.77) U1.T18 ; U1.V12 58.05,75.57 v3(57.65,75.97) ; U1.H12 v3(66.45,75.16) ; U1.J11 v3(65.65,74.36) ; U1.R7 v3(60.85,71.16) ; U1.J18 v3(64.85,80.77) U1.K18 64.05,80.76 v3(64.05,80.77) U1.L18 63.65,80.36 v3(63.25,79.97) U1.M17 U1.N17 ; U1.T6 v3(60.05,71.16) ; U1.R6 v3(60.05,70.36) ; U1.J13 v3(65.65,76.77) ; U1.H17 v3(66.45,79.97)
  BOTTOM w0.279: U1.M7 v3(63.25,71.16) ; U1.U11 v3(58.45,74.36) ; U1.U9 v3(58.45,72.76)
  BOTTOM w0.356: U1.U14 v3(58.45,77.57)
  BOTTOM w0.381: v3(58.45,78.37) U1.V15 v3(58.45,77.57) ; v3(58.45,78.37) U1.U15 ; v3(58.45,78.37) U1.U16 v3(58.45,79.17) ; U1.U17 v3(58.45,79.17) ; v3(58.45,79.17) 58.05,78.77 U1.V16 v3(57.65,78.37)
  vias: v2(29.54,89.03) v2(29.54,88.27) v2(29.54,87.38) v2(29.54,86.49) v2(30.56,89.03) v2(30.56,88.27) v2(30.56,87.38) v2(30.56,86.49) v2(42.04,91.08) v2(42.04,90.37) v2(41.99,89.56) v2(42.45,88.87) v2(42.42,88.11) v2(42.47,87.43) v4(33.02,92.46)
P0V9_AGND: length 4.1
  TOP w0.305: v2(67.94,43.01) PU23.4 69.45,43.03 70.16,43.03 v2(70.32,43.18) 71.96,43.18 PR423.2
P0V9_COMP: length 6.6
  TOP w0.254: PR427.1 73.44,43.71 v1(73.2,43.95) 72.78,43.53 72.78,42.54 72.53,42.28 PC589.1 70.71,42.6 70.05,42.6 69.82,42.36 PU23.3
P0V9_COMP_RC: length 2.6
  TOP w0.254: PR427.2 74.24,41.72 v1(74.01,41.49) 73.03,41.49 PC591.1
P0V9_EN: length 7.6
  TOP w0.203: v2(70.19,38.24) 70.11,38.32 70.11,38.85 69.25,39.72 68.28,39.72 67.95,40.05 PU23.15
  TOP w0.254: PC580.1 70.8,37.64 v2(70.19,38.24)
  BOTTOM w0.254: v2(70.19,38.24) 70.68,38.73 v4(71.32,38.73) 71.34,38.72 PR418.2
P0V9_FB: length 7.8
  TOP w0.254: PC589.2 71.25,41.72 PC591.2 ; PC589.2 PR431.1 72.24,40.53 v1(72.25,40.51) 72.47,40.3 PR432.1 ; PC589.2 70.84,41.48 70.57,41.22 70.46,41.22 v2(70.31,41.06) PU23.1
  BOTTOM w0.254: PR429.2 69.31,41.91 70.16,41.06 v2(70.31,41.06)
P0V9_FB_RC: length 2.8
  TOP w0.254: PR431.2 71.02,38.69 v1(71.17,38.54) 71.91,39.27 PC597.1
P0V9_PG: length 281.9
  TOP w0.114: PR420.2 v2(71.44,47.72) ; v2(300.79,24.1) 302.88,22.01 Q7.G ; v2(298.27,42.75) 298.12,42.75 294.7,46.17 R297.1
  TOP w0.254: PU23.7 69.63,44.96 69.75,45.09 69.75,45.82 70.98,47.05 PR420.2
  IN2 w0.147: v2(300.79,24.1) 300.79,28.24 298.27,30.76 v2(298.27,42.75)
  BOTTOM w0.114: v2(300.79,24.1) 297.77,24.1 296.39,22.73 291.62,22.73 291.14,22.25 282.53,22.25 281.69,23.09 274.63,23.09 272.95,24.77 268.23,24.77 266.7,26.29 189.13,26.29 168.78,46.63 118.42,46.63 115.29,43.51 74.73,43.51 71.44,46.8 v2(71.44,47.72)
P0V9_PG_LED_H: length 2.2
  TOP w0.114: R110.1 304.64,25.4 v2(305.26,25.4) 305.64,25.78 D1.A
P0V9_PG_LED_N: length 4.6
  TOP w0.114: Q7.D 305.6,23.62 v2(306.91,23.62) 307.27,23.98 R109.2 307.27,25.15 307.66,25.53 D1.C
P0V9_RT: length 2.8
  TOP w0.254: PU23.5 69.83,43.66 70.3,44.14 v1(70.76,44.14) 71.88,44.14 PR423.1
P0V9_SENSE_R_N: length 68.8
  TOP w0.254: PR505.1 46.03,59.66 45.52,59.66 v2(45.34,59.49)
  BOTTOM w0.254: PR428.1 68.34,43.74 PR504.2 68.53,43.54 68.53,42.06 PR429.1 68.43,41.87 68.43,41.71 68.9,41.24 69.28,41.24 70.05,40.46 71.5,40.46 v4(72.62,39.34) 72.62,38.38 73.74,37.26 73.74,36.68 71.6,34.54 47.25,34.54 45.14,36.66 45.14,45.31 44.27,46.18 44.27,59.26 44.71,59.69 45.14,59.69 v2(45.34,59.49) 45.52,59.66 46.03,59.66 PR505.1
P0V9_SENSE_R_P: length 63.3
  TOP w0.254: v2(45.37,60.25) 45.54,60.07 46.29,60.07 PR433.1 ; PC597.2 v2(73.59,38.47) 73.59,39.37 PR432.2
  BOTTOM w0.254: PR433.1 46.29,60.07 45.54,60.07 v2(45.37,60.25) 45.19,60.07 44.55,60.07 43.89,59.42 43.89,46.02 44.76,45.16 44.76,36.5 47.09,34.16 71.76,34.16 74.12,36.53 74.12,37.94 v2(73.59,38.47)
P0V9_VCC: length 9
  TOP w0.254: v2(67.41,46.58) 67.3,46.47 PU23.10 ; PU23.6 69.84,44.31 70.79,45.26 v7(70.79,45.68)
  TOP w0.381: v2(67.41,46.58) 67.41,47.27 PC581.2
  IN1 w0.254: v7(70.79,45.68) 70.31,45.2 68.06,45.2 67.6,45.66 67.6,46.39 v2(67.41,46.58)
P0V9_VIN: length 4.1
  TOP w0.254: PU23.9 67.95,46.38 v2(68.12,46.55)
  TOP w0.381: PC583.1 68.41,46.85 v2(68.12,46.55)
  BOTTOM w0.508: v2(68.12,46.55) 68.12,47.45 PR426.2
P0V9_VREF: length 2.2
  TOP w0.254: v2(70.31,41.88) 70.25,41.88 70.08,41.71 PU23.2
  BOTTOM w0.254: PC582.1 70.56,42.14 70.31,41.89 v2(70.31,41.88)
P0V9_VSNS: length 4.5
  TOP w0.254: v2(69.49,46.35) 69.03,46.35 68.6,45.92 PU23.8
  BOTTOM w0.254: PR428.2 68.34,45.63 69.04,46.34 69.48,46.34 v2(69.49,46.35) 69.49,46.82 69.2,47.11 PR430.1
P1V8: length 301.8
  TOP w0.203: 65.44,80.28 v3(65.65,79.97) ; v3(61.65,80.77) 61.42,81 C131.1 ; C135.1 v3(59.25,71.16) ; C53.1 v3(61.65,70.36) ; C133.1 v3(64.85,71.16) ; C139.1 v3(59.25,79.97)
  TOP w0.254: v3(61.65,80.77) 61.67,80.75 R57.1 ; C129.1 58.5,75.21 v3(58.45,75.16) ; C181.1 v3(65.65,75.16) ; U12.1 v2(121.07,39.22)
  TOP w0.356: U13.5 158.21,113.78 158.47,113.53 C191.1 ; R60.1 R62.1
  TOP w0.381: v2(65.74,62.87) 65.36,63.25 R94.1 ; v2(63.98,100.69) C1.1 64.85,100.33 64.34,99.82 U6.8 ; R47.1 61.04,63.12 v2(61.16,62.99) ; R113.1 v2(23.83,108.97) ; R51.1 v2(30.18,108.97) ; R117.1 v2(56.97,93.34) R70.1 ; R49.1 v2(33.22,106.93) R69.1 ; R54.1 R50.1 58.88,63.32 59.26,62.94 v2(59.64,62.94) ; R52.1 v2(25.86,106.81) ; C191.1 158.47,111.99 v2(158.57,111.89) ; v2(54.81,62.94) R74.1 R72.1 ; R64.1 v2(35,108.35) ; C127.1 v2(52.66,95.38) ; R55.1 v2(24.84,106.81) R56.1 ; v2(62.82,62.99) 63.07,63.25 R53.1 ; v2(258.24,27.15) 258.52,26.87 R146.1 ; v2(63.81,87.93) 64.21,88.34 R128.1 R121.1 ; v2(77.93,74.17) 77.67,74.42 R60.1 ; R129.1 v2(66.73,101.49) ; R48.1 v2(57.99,95.38) ; R111.1 v2(68.4,62.89) ; R351.1 v2(165.3,114.7) ; R46.1 v2(70.44,62.89) ; R115.1 v2(53.67,95.38) ; R93.1 v2(69.42,62.89)
  TOP w0.457: v2(70.46,91.69) 70.46,92.55 C48.1 71.35,92.62 v2(71.35,91.69) ; R120.1 67.39,88.37 v2(67.16,88.14)
  IN1 w0.762: v2(121.07,39.22) 122,39.22 122.81,40.03 125.3,40.03 129.08,43.81 170.51,43.81 186.89,27.43 257.51,27.43 257.79,27.15 v2(258.24,27.15)
  IN2 w0.508: v2(165.3,114.7) 161.39,114.7 v2(158.57,111.89) 154.94,108.25 71.01,108.25 66.73,103.97 v2(66.73,101.49) 65.93,100.69 v2(63.98,100.69)
  BOTTOM w0.254: U1.T7 v3(59.25,71.16) ; v3(59.25,79.97) 59.65,79.57 U1.T17 ; U1.K7 v3(64.85,71.16) ; U1.N6 v3(61.65,70.36) ; U1.N18 v3(61.65,80.77) ; U1.J12 v3(65.65,75.16) ; U1.J17 v3(65.65,79.97)
  BOTTOM w0.279: U1.U12 v3(58.45,75.16)
  BOTTOM w0.381: R278.1 R277.1 C451.1 121.11,39.26 v2(121.07,39.22)
  vias: v2(46.31,94.36) v2(46.31,93.47) v2(46.31,92.46) v2(47.19,93.47) v2(47.19,92.46) v2(59.03,106.17) v2(59.03,105.41) v2(59.92,106.17) v2(59.92,105.41) v2(60.81,106.17) v2(60.81,105.41) v2(60.81,104.65) v4(57.74,105.54)
P1V8_A: length 7.4
  TOP w0.203: C138.1 v3(64.05,79.97) ; v3(58.45,76.77) C134.1 ; C132.1 v3(64.05,71.16) ; C130.1 v3(58.45,73.56) ; v3(58.45,71.16) 58.22,70.93 C128.1 ; C140.1 v3(65.65,77.57) ; C136.1 v3(60.05,79.97)
  BOTTOM w0.254: U1.L7 v3(64.05,71.16) ; U1.J14 v3(65.65,77.57) ; v3(60.05,79.97) 60.45,79.57 U1.R17 ; U1.U13 v3(58.45,76.77) ; U1.J10 v3(65.65,73.56) ; U1.L17 v3(64.05,79.97) ; v3(58.45,73.56) 58.85,73.96 U1.U10
  BOTTOM w0.279: U1.U7 v3(58.45,71.16)
  vias: v1(50.88,89) v2(49.99,87.63) v2(50.12,89.53) v2(50.12,88.52) v2(51.03,93.24) v2(51,91.31) v2(51,90.68) v2(51.06,92.28)
P1V8_AGND: length 5.1
  TOP w0.254: v2(43.25,105.82) 43.09,105.66 PR368.2
  TOP w0.305: v2(45.32,106.16) 45.07,105.91 PU19.4 43.34,105.91 v2(43.25,105.82)
  BOTTOM w0.305: v2(43.25,105.82) 43.25,105.87 v4(42.72,106.4) 42.38,106.05 PR372.1
P1V8_COMP: length 4.4
  TOP w0.254: PU19.3 42.78,106.41 42.6,106.59 PC547.1 41.82,106.59 v1(41.33,106.1) 40.38,106.1 PR371.1
P1V8_COMP_RC: length 2.9
  TOP w0.254: PR371.2 39.3,107.5 v1(39.52,107.72) 39.87,107.37 PC549.1
P1V8_EN: length 17.9
  TOP w0.254: v2(44.7,108.62) 44.82,108.5 PU19.15
  IN2 w0.254: v2(44.7,108.62) 44.4,108.92 44.4,110.24 44.14,110.49 42.7,110.49 40.97,108.76 40.97,106.55 39.83,105.41 v2(37.67,105.41)
  BOTTOM w0.114: v2(37.67,105.41) 38.43,105.41 38.56,105.28 39.7,105.28 39.81,105.17 PR361.1
  BOTTOM w0.127: PR357.2 39.49,104.72 39.81,105.04 PR361.1
  BOTTOM w0.254: PC539.1 44.45,107.65 44.7,107.91 v2(44.7,108.62)
P1V8_FB: length 7.7
  TOP w0.254: PC547.2 42.57,107.37 PC549.2 ; PC547.2 PR373.1 42.55,108.36 PR374.1 ; PC547.2 42.73,107.39 43.08,107.73 43.25,107.73 v2(43.28,107.75) 43.36,107.75 43.7,107.41 PU19.1
  BOTTOM w0.254: v2(43.28,107.75) 43.03,108 v4(41.53,108) PR372.2
P1V8_FB_RC: length 3.3
  TOP w0.254: PR373.2 42.58,110.03 42.02,110.59 v1(41.63,110.59) PC555.1
P1V8_PG: length 185.8
  TOP w0.114: PR363.2 40.72,103.25 40.21,103.76 v2(40.21,104.27) 41.73,104.27 41.84,104.17 43.87,104.17 44.07,104.37 PU19.6
  IN2 w0.147: v2(40.21,104.27) 40.16,104.27 39.6,103.71 37.16,103.71 34.55,101.09 27.8,101.09 18.37,91.66 18.37,64.85 17.83,64.31 17.83,53.11 21.15,49.8 36.56,49.8 45.19,41.17 45.19,37.03 48.3,33.92 68.06,33.92 v2(70.18,36.04) v2(118.19,36.04)
  BOTTOM w0.114: v2(118.19,36.04) 118.31,35.92 R276.2
  BOTTOM w0.254: PR418.1 70.78,36.64 v2(70.18,36.04)
P1V8_RT: length 1.7
  TOP w0.254: PR368.1 43.08,104.86 43.62,105.41 PU19.5
P1V8_SS: length 5.6
  TOP w0.254: v2(43.3,106.94) 43.34,106.91 PU19.2
  BOTTOM w0.254: PR366.2 45.69,105.23 45.97,105.51 45.97,106.35 45.38,106.95 v4(45.2,106.95) 44.68,106.95 44.45,106.71 PR367.1 43.53,106.71 v2(43.3,106.94)
P1V8_VCC: length 4.3
  TOP w0.254: PU19.8 45.32,103.81 v2(45.46,103.66)
  TOP w0.305: v2(45.46,103.66) 45.72,103.41 PC541.1
  BOTTOM w0.254: PR366.1 46.27,104.43 v4(46.38,104.32) 45.71,103.66 v2(45.46,103.66)
P1V8_VIN: length 4.7
  TOP w0.254: v2(44.57,103.69) 44.82,103.93 PU19.7
  TOP w0.305: v2(44.57,103.69) 44.42,103.54 PC542.1
  BOTTOM w0.305: v2(44.57,103.69) 44.57,103.05 PR370.2 45.39,102.23 v4(46.33,102.23)
P1V8_VSENSE_R: length 28.2
  TOP w0.254: v2(39.63,109.73) 39.63,109.7 39.99,109.33 PC555.2 PR374.2 ; PR375.1 v2(60.94,109.55)
  IN2 w0.254: v2(39.63,109.73) 39.63,110.14 42.77,113.28 57.74,113.28 60.94,110.08 v2(60.94,109.55)
P3V3: length 287.5
  TOP w0.254: v2(276.81,111.71) 276.81,112.73 280.01,115.93 303.25,115.93 304.7,114.48 304.7,110.06 303.15,108.51 303.15,102.46 302.11,101.42 PR345.2 ; PR420.1 v2(72.24,47.75) ; PR348.2 303,113.89 302.08,114.81 280.67,114.81 v2(277.57,111.71)
  TOP w0.356: U11.5 278.83,30.19 C172.1 ; R154.1 v2(284.81,42.04) ; U16.5 281.62,70.73 C455.1
  TOP w0.381: v2(315.98,32.08) 315.79,31.9 R193.1 ; v2(313.01,28.7) 312.64,29.06 R163.1 ; R110.2 v2(302.85,25.78) ; PR363.1 41.75,101.58 ; R4.1 v2(298.51,50.87) ; R209.1 v2(122.51,42.55) ; R161.1 121.72,35.46 v2(121.8,35.54) R194.1 ; R3.1 v2(297.06,45.39) ; R155.1 v2(284.81,82.52) ; v2(290.93,69.72) R159.1 ; R153.1 v2(288.04,65.21) ; C455.1 v2(280.85,70.85) ; R156.1 v2(295.51,69.09) ; U17.5 281.64,29.06 C456.1 v2(280.89,30.21) ; R164.1 v2(276.68,24.49) ; R191.1 123.55,43.56 v2(123.52,43.59) ; U12.8 v2(121.07,34.77) ; R204.1 v2(310.72,31.9) ; R107.1 v2(295.96,68.22) ; R147.1 v2(262.46,24.43) ; R160.1 v2(316.5,30.12) ; R6.1 v2(295.1,60.02) ; R137.1 v2(295.1,57.99)
  TOP w0.457: R317.1 v2(280.11,31.65) ; C172.1 v2(278.16,30.21)
  TOP w0.508: R109.1 v2(308.07,23.9) ; R192.1 289.91,25.93 v2(290.15,26.16) R210.1 ; R304.1 289.13,23.13 289.36,23.37 R342.1 v2(289.36,24.38) ; v2(165.3,111.51) 165.32,111.53 R348.1 ; R203.1 296.24,26.72 296.42,26.54 v2(296.42,26.31) 296.45,26.31 296.45,25.5 296.22,25.27 R162.1 ; R303.1 295.23,23.11 295.46,23.35 R301.1 v2(295.46,24.38)
  TOP w0.762: 41.75,101.58 43.13,100.2 60.28,100.2 64.67,104.59 72.59,104.59 75.17,107.17 v2(75.17,109.52) ; CON1.1 v2(188.7,115.78)
  IN1 w0.762: v2(75.17,109.52) 78.73,113.08 163.73,113.08 v2(165.3,111.51) 165.3,108.71 171.02,103 186.89,103 189.82,105.92 189.82,114.66 v2(188.7,115.78)
  BOTTOM w0.254: v2(302.09,102.73) 302.03,102.67 PR336.1
  BOTTOM w0.381: v2(121.07,34.77) 121.11,34.81 C450.1 ; R296.1 v2(120.09,34.78)
  vias: v2(276.81,109.55) v2(276.81,107.39) v2(276.81,105.23) v2(276.81,103.07) v2(276.81,100.91) v2(276.81,98.76) v2(277.57,109.55) v2(277.57,107.39) v2(277.57,105.23) v2(277.57,103.07) v2(277.57,100.91) v2(277.57,98.76) v2(285.65,32.36) v2(285.83,72.9) v2(287.35,31.88) v2(287.48,72.52) v2(288.24,31.88) v2(288.49,72.52) v2(307.68,54.05) v2(307.68,53.29) v4(277.7,114.43)
P3V3_AGND: length 6.9
  TOP w0.254: v2(299.62,105.27) 299.63,105.27 299.73,105.17 PR344.1
  BOTTOM w0.254: 296.92,105.75 PU17.4 298.88,105.75 299.36,105.27 v2(299.62,105.27) 299.87,105.27 301.07,104.06 301.65,104.06 301.91,103.81 PR339.2 ; 296.92,105.75 v2(296.88,105.79) ; 296.92,105.75 PU17.17
  vias: v1(297.64,106.22)
P3V3_BUF_VDDA:
  vias: v2(294.98,56.08)
P3V3_BUF_VDDR: length 2.1
  TOP w0.178: C227.1 300.29,54.79 300.51,55.01 U9.5 300.51,56.32
P3V3_CLK_BUF_VDD: length 24.5
  TOP w0.178: 303.09,57.3 U9.12 303.77,57.3 C217.1 ; C216.1 296.62,58.9 U9.35 298.34,58.9 ; 299.31,61.07 U9.29 299.31,61.58 298.42,62.47 C219.1 ; C257.1 304.45,61.39 303.56,60.5 U9.20 303.09,60.5 ; C222.1 302.51,61.76 U9.21 302.51,61.07 ; 300.91,61.07 U9.25 300.91,62.26 300.68,62.49 C218.1 ; 298.34,60.5 U9.31 297.05,60.5 C221.1 ; C220.1 296.85,57.3 U9.39 298.34,57.3 ; C258.1 304.5,59.13 304.27,58.9 U9.16 303.09,58.9
  TOP w0.381: C221.1 296.77,61.29 v2(297.13,61.29) ; C258.1 304.73,58.89 v2(305.11,58.52) ; v2(297.13,59.38) 296.9,59.38 C216.1 ; R1.1 v2(296.85,52.89) ; R91.1 v2(301.34,51.11) ; C220.1 296.77,56.72 v2(297.13,56.72) ; v2(304.94,60.72) 304.73,60.93 C257.1 ; v2(303.87,62.47) C222.1 ; v2(297.76,62.72) C219.1 ; C218.1 300.92,62.72 v2(301.29,63.1)
  TOP w0.457: R92.1 v2(294.98,54.05)
  vias: v2(304.5,52.53) v2(305.26,52.53) v4(295.94,51.03) v4(296.27,63.2) v4(305.16,54.56)
P3V3_COMP: length 5.4
  BOTTOM w0.254: PU17.3 298.99,106.25 299.44,105.79 299.75,105.79 299.99,106.03 PC516.1 300.3,105.7 v4(301.33,104.67) 301.33,105.75 PR342.1
P3V3_COMP_RC: length 3.8
  BOTTOM w0.254: PR342.2 302.05,105.6 302.39,105.26 v4(303.05,105.26) 303.02,105.28 303.02,106.56 302.77,106.82 PC518.1
P3V3_EN: length 9.5
  TOP w0.254: v2(299.92,109.98) 299.67,110.24 299.67,110.6 299.94,110.87 PR332.2
  BOTTOM w0.127: PC506.1 299.91,112.73 300.21,113.03 v4(300.46,113.03)
  BOTTOM w0.203: v2(299.92,109.98) 299.92,109.78 298.55,108.41 297.26,108.41 296.91,108.06 PU17.15
  BOTTOM w0.254: PC506.1 299.9,111.74 PR333.1 299.9,110 v2(299.92,109.98)
P3V3_FB: length 6.9
  TOP w0.254: v7(299.6,107.31) 300.31,106.61 PR344.2
  BOTTOM w0.254: PU17.1 299.53,107.25 v7(299.6,107.31) 299.78,107.31 300.26,106.83 PC516.2 ; PC518.2 301.25,106.83 PC516.2 ; PC516.2 PR346.1 300.32,107.81 PR347.1
P3V3_FB_RC: length 1.9
  BOTTOM w0.254: PR346.2 300.24,108.65 300.24,109.15 v7(300.43,109.35) 300.53,109.25 300.78,109.25 PC527.1
P3V3_MB: length 1.6
  TOP w0.508: R360.1 285.87,22.75 C169.1
  vias: v2(286.34,21.34) v2(287.1,21.34) v2(287.86,21.34) v2(288.37,9.27) v2(288.37,8.51) v2(288.37,7.77) v2(288.37,7.11) v2(289.03,9.27) v2(289.03,8.51) v2(289.03,7.77) v2(289.03,7.11)
P3V3_PG: length 469.5
  TOP w0.114: v2(285.85,51.51) 286.41,52.07 296.85,52.07 R298.1
  IN2 w0.147: v2(37.54,103) 37.42,103 34.75,100.33 27.71,100.33 18.87,91.49 18.87,64.57 18.32,64.01 18.32,53.39 21.31,50.39 36.81,50.39 52.68,34.52 67.82,34.52 69.88,36.58 74.3,36.58 81.18,43.46 93.03,43.46 104.95,55.38 153.64,55.38 180.69,28.33 255.4,28.33 257.69,26.04 260.17,26.04 262.47,28.33 263.85,28.33 264.71,27.47 276.45,27.47 278.08,29.1 280.81,29.1 284.43,32.72 284.43,34.02 283.57,34.87 283.41,34.87 281.89,36.4 281.54,36.4 280.9,37.03 280.9,38.15 281.64,38.89 281.64,47.29 v2(285.85,51.51) 285.85,56.52 284.43,57.94 284.43,61.52 280.09,65.86 280.09,73 279.83,73.25 279.83,73.7 280.31,74.84 280.9,76.28 280.9,78.74 281.76,79.6 281.76,84.18 282.3,84.71 282.3,87.48 v2(281.31,88.47)
  BOTTOM w0.114: PR336.2 301.23,97.75 295.4,91.92 284.76,91.92 v2(281.31,88.47)
  BOTTOM w0.127: v2(37.54,103) 37.86,103.13 PR357.1
  BOTTOM w0.254: PR336.2 299.44,101.88 298.83,102.49 298.83,103.89 298.47,104.25 PU17.7
P3V3_RT: length 3.6
  BOTTOM w0.254: PR339.1 300.92,103.5 300.13,104.3 v4(299.96,104.3) 299.78,104.3 298.83,105.25 PU17.5
P3V3_SENSE_R: length 4.2
  TOP w0.254: PR348.1 v2(303,110.11)
  BOTTOM w0.254: PR347.2 PC527.2 302.05,109.59 302.57,110.11 v2(303,110.11)
P3V3_STBY_MB: length 184.9
  TOP w0.254: C352.1 286.68,58.82 U8.5 ; 263.22,27.58 U3.8 ; U10.1 179.27,80.01 v2(179.54,80.27)
  TOP w0.305: C223.1 308.47,36.28 308.04,35.85 U2.24
  TOP w0.356: C460.1 285.82,86.37 U19.5 ; C159.1 277.33,25.4 U47.5 ; C461.1 285.82,45.86 U20.5
  TOP w0.381: v2(268.64,26) C179.1 C178.1 263.48,26.72 263.22,26.98 263.22,27.58 ; v2(284.33,57.2) 284.58,56.95 R309.1 ; R258.1 R259.1 v2(289.51,70.23) ; C159.1 v2(278.1,25.29) ; R293.1 v2(313.89,30.45) ; R97.1 v2(305.39,46.86) ; R100.1 v2(301.96,46.89) ; v2(305.94,27.79) R186.1 R185.1 ; R79.1 v2(306.96,27.79) ; R263.1 R264.1 v2(289.38,29.21) ; v2(304.24,46.89) R98.1 R99.1 ; R87.1 v2(307.98,31.98) ; v2(286.46,59.74) 286.7,59.51 C352.1 ; R145.1 v2(299.54,26.01) ; R83.1 v2(309.96,46.89) ; R283.1 v2(313.89,46.91) ; v2(300.15,27.89) R103.1 ; R101.1 v2(300,46.25) R102.1 ; v2(315.91,33.67) C452.1 U7.8 ; R262.1 v2(291.42,29.46) ; C223.1 v2(309.12,35.66) ; R285.1 v2(311.91,46.25) ; R150.1 R151.1 189.36,76.96 v2(189.38,76.94) 189.41,76.96 200.18,76.96 214.61,91.39 280.47,91.39 v2(284.1,87.76) ; R96.1 v2(306.53,46.86) ; R81.1 v2(308.81,46.89) ; R257.1 v2(291.54,70.23) ; R106.1 v2(303.86,27.81) ; R144.1 v2(297.85,26.65) ; R105.1 v2(302.85,27.81) ; R281.1 v2(315.85,46.25) ; R88.1 v2(308.99,31.98) ; R78.1 v2(307.67,44.63) ; R104.1 v2(301.27,27.87) ; v2(307.67,46.89) R95.1
  TOP w0.457: R359.1 R357.1 v2(289.89,12.09) ; C461.1 v2(285.83,46.53) ; R356.1 287.22,11.76 v2(287.56,12.09) ; C460.1 v2(285.83,87.05) ; R261.1 v2(287.86,44.09)
  TOP w0.508: R252.1 v2(287.86,84.71)
  BOTTOM w0.254: C259.1 307.29,77.34 306.87,77.76 U4.1
  BOTTOM w0.381: v2(189.38,76.94) 189.38,80.04 188.42,81 179.07,81 C265.1 v2(179.54,80.27) ; R302.1 v2(309.07,81.15) ; R341.1 v2(314.4,80.14) ; C259.1 v2(306.55,76.35)
  BOTTOM w0.762: J5.B10 286.83,6.02 287.08,6.27 287.08,6.29 287.13,6.34 287.13,8.77 287.08,8.82 287.08,8.91 285.22,10.77 285.22,12.55
  vias: v2(283.54,13.84) v2(283.92,21.34) v2(284.3,14.22) v2(284.3,13.59) v2(284.3,12.83) v2(284.43,20.7) v2(286.84,42.04)
P3V3_VCC: length 10.2
  IN1 w0.254: v7(296.3,102.08) 297.26,103.05 299.28,103.05 v2(299.63,102.7)
  BOTTOM w0.254: v2(299.63,102.7) 299.32,103.01 299.32,104.14 298.71,104.75 PU17.6 ; v7(296.3,102.08) 296.3,102.57 296.41,102.68 PU17.10
  BOTTOM w0.381: v7(296.3,102.08) 296.3,101.96 297.03,101.22 PC508.2
P3V3_VIN: length 5.3
  TOP w0.381: v7(297.59,102.08) 296.86,101.34 PR341.2
  BOTTOM w0.254: PU17.9 296.91,102.77 v7(297.59,102.08)
  BOTTOM w0.381: PC510.1 298.33,100.92 297.59,101.66 v7(297.59,102.08)
P3V3_VREF: length 2.4
  TOP w0.254: v2(299.57,106.38) 299.24,106.05 PC509.1
  BOTTOM w0.254: PU17.2 299.21,106.75 v2(299.57,106.38)
P3V3_VSNS: length 6.3
  TOP w0.254: PR343.2 297.69,103.68 v1(298.74,102.64) 298.76,102.62 298.76,102.09 v2(298.52,101.85) 299.31,101.85 PR345.1
  BOTTOM w0.254: PU17.8 297.41,103.21 298.52,102.1 v2(298.52,101.85)
P12V: length 0.9
  TOP w0.254: v2(301.48,111.67) PR332.1
  vias: v2(1.91,93.78) v2(2.03,92.76) v2(1.96,88.9) v2(2.08,87.88) v2(3.48,88.72) v2(3.61,87.71) v2(3.66,96.24) v2(3.79,95.22) v2(4.42,98.91) v2(4.55,97.89) v2(5.21,88.87) v2(5.34,87.86) v2(6.48,89.53) v2(6.61,88.52) v2(7.19,104.65) v2(7.32,91.95) v2(7.44,101.98) v2(7.44,95.12) v2(7.57,104.01) v2(7.57,100.58) v2(7.57,99.06) v2(7.57,97.92) v2(7.57,94.11) v2(7.57,92.96) v2(7.7,96.01) v2(7.82,103.12) v2(8.21,97.16) v2(8.59,102.62) v2(8.59,99.95) v2(8.71,93.85) v2(9.35,103.12) v2(9.48,96.9) v2(9.6,93.47) v2(9.73,102.49) v2(9.86,100.33) v2(9.86,99.57) v2(9.98,94.49) v2(10.11,96.01) v2(10.24,105.16) v2(10.24,104.27) v2(10.24,103.38) v2(10.24,101.73) v2(10.24,97.92) v2(10.24,92.58) v2(13.03,100.2) v2(13.03,99.31) v2(13.03,94.36) v2(13.03,93.47) v2(53.24,36.98) v2(53.24,36.32) v2(53.81,37.35) v2(53.82,36.68) v2(53.82,35.92) v2(285.1,112.27) v2(285.1,111.51) v2(285.68,112.57) v2(285.66,111.86) v2(285.66,111.18) v2(293.42,32) v2(293.57,72.52) v2(294.06,31.95) v2(294.34,41.83) v2(294.97,41.81) v2(295.56,83.82) v2(295.61,83.16) v2(295.86,33.53) v2(295.86,32.77) v4(285.57,113.49)
P12V_MB: length 3.3
  BOTTOM w0.508: J5.B1 295.83,5.7 295.05,6.48
  vias: v2(293.14,7.87) v2(293.14,7.11) v2(293.8,8.61) v2(293.8,7.87) v2(293.8,7.11) v2(294.34,11.81) v2(294.46,8.61) v2(294.46,7.87) v2(294.46,7.11) v2(294.59,13.97) v2(294.97,18.41) v2(294.97,16.51) v2(295.73,13.59) v2(296.11,18.54) v2(296.5,16.38) v2(297.64,14.22) v2(300.05,19.05) v2(300.05,18.29) v2(300.05,17.63) v2(300.05,16.97) v2(300.05,16.26)
P12V_PSU:
  vias: v2(12.4,86.74) v2(13.03,87.25) v2(13.03,86.36)
85OHM_BOT_5INCH_DN: length 127
  BOTTOM w0.135: U41.2 -13.97,200.55 -13.97,203.4 -13.38,204.24 -12.51,204.4 -9.32,203.83 -9.2,203.92 -9.09,204.56 -9.21,204.73 -16.35,205.99 -16.68,206.45 -16.55,207.18 -16.12,207.47 -7.86,206.02 -7.72,206.12 -7.61,206.73 -7.66,206.81 -7.71,206.87 -7.73,206.91 -7.78,206.92 -7.89,206.94 -17.4,208.62 -17.72,209.08 -17.6,209.8 -17.17,210.1 -7.87,208.46 -7.7,208.58 -7.61,209.14 -7.76,209.35 -17.38,211.05 -17.65,211.44 -17.51,212.26 -17.11,212.53 -8.7,211.05 -8.53,211.17 -8.43,211.72 -8.58,211.94 -17.48,213.51 -17.75,213.89 -17.6,214.73 -17.21,214.99 -7.9,213.35 -7.68,213.51 -7.6,213.96 -7.8,214.24 -17.63,215.98 -17.91,216.37 -17.77,217.15 -17.34,217.46 -7.72,215.76 -7.51,215.91 -7.42,216.43 -7.57,216.64 -14.93,217.94 -15.15,218.26 -14.93,219.5 -14.93,221.74 U39.1
85OHM_BOT_5INCH_DP: length 127
  BOTTOM w0.135: U41.1 -13.67,200.56 -13.67,203.31 -13.21,203.96 -12.51,204.09 -9.25,203.51 -9.02,203.67 -8.92,203.74 -8.76,204.63 -9.03,205 -16.18,206.26 -16.35,206.52 -16.27,207 -16.05,207.15 -7.79,205.7 -7.61,205.82 -7.44,205.94 -7.29,206.8 -7.41,206.98 -7.48,207.09 -7.56,207.19 -17.23,208.9 -17.4,209.15 -17.32,209.62 -17.09,209.78 -7.8,208.14 -7.42,208.4 -7.28,209.21 -7.58,209.63 -17.2,211.33 -17.33,211.51 -17.23,212.08 -17.04,212.21 -8.63,210.73 -8.25,210.99 -8.11,211.79 -8.4,212.22 -10.18,212.53 -17.31,213.79 -17.43,213.96 -17.32,214.54 -17.14,214.67 -7.83,213.03 -7.41,213.33 -7.28,214.03 -7.62,214.52 -17.45,216.26 -17.59,216.44 -17.49,216.97 -17.27,217.13 -7.65,215.44 -7.23,215.73 -7.1,216.5 -7.39,216.92 -14.75,218.22 -14.83,218.33 -14.63,219.48 -14.63,221.75 U39.2
